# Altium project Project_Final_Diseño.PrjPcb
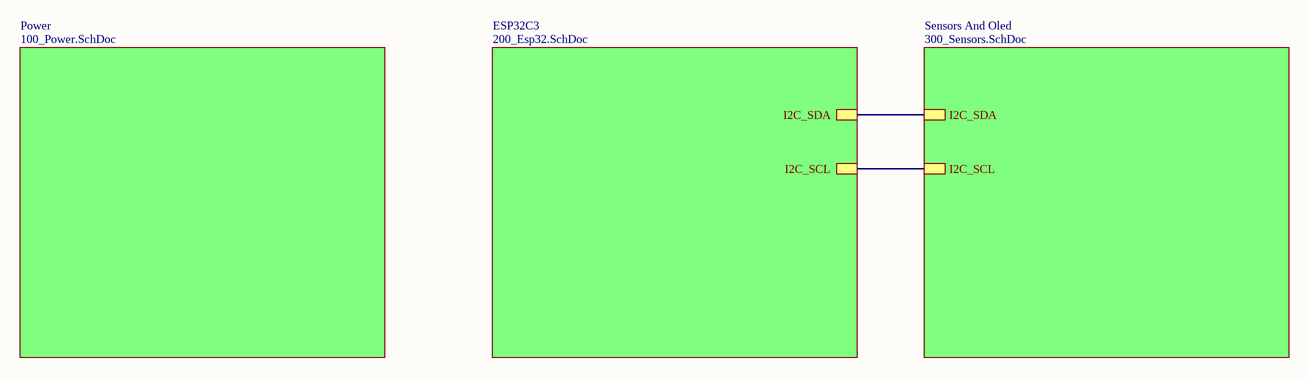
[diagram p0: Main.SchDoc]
4 sheets, 49 parts. Net scope: hierarchical (ports join the sheet entries above them; power ports are global).
Board file: PCB_FINALPcbDoc.PcbDoc
Sheets:
  Main.SchDoc
    Power = 100_Power.SchDoc
    ESP32C3 = 200_Esp32.SchDoc
    Sensors And Oled = 300_Sensors.SchDoc

## Sheet Main.SchDoc
size A4; SheetNumber: 1; SheetTotal: 4

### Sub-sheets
ESP32C3 = 200_Esp32.SchDoc: I2C_SDA, I2C_SCL
Power = 100_Power.SchDoc: no entries
Sensors And Oled = 300_Sensors.SchDoc: I2C_SDA, I2C_SCL

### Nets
NetU203_5: sheet ESP32C3/I2C_SDA, sheet Sensors And Oled/I2C_SDA
NetU203_6: sheet ESP32C3/I2C_SCL, sheet Sensors And Oled/I2C_SCL

## Sheet 100_Power.SchDoc
size A4; SheetNumber: 2; SheetTotal: 4
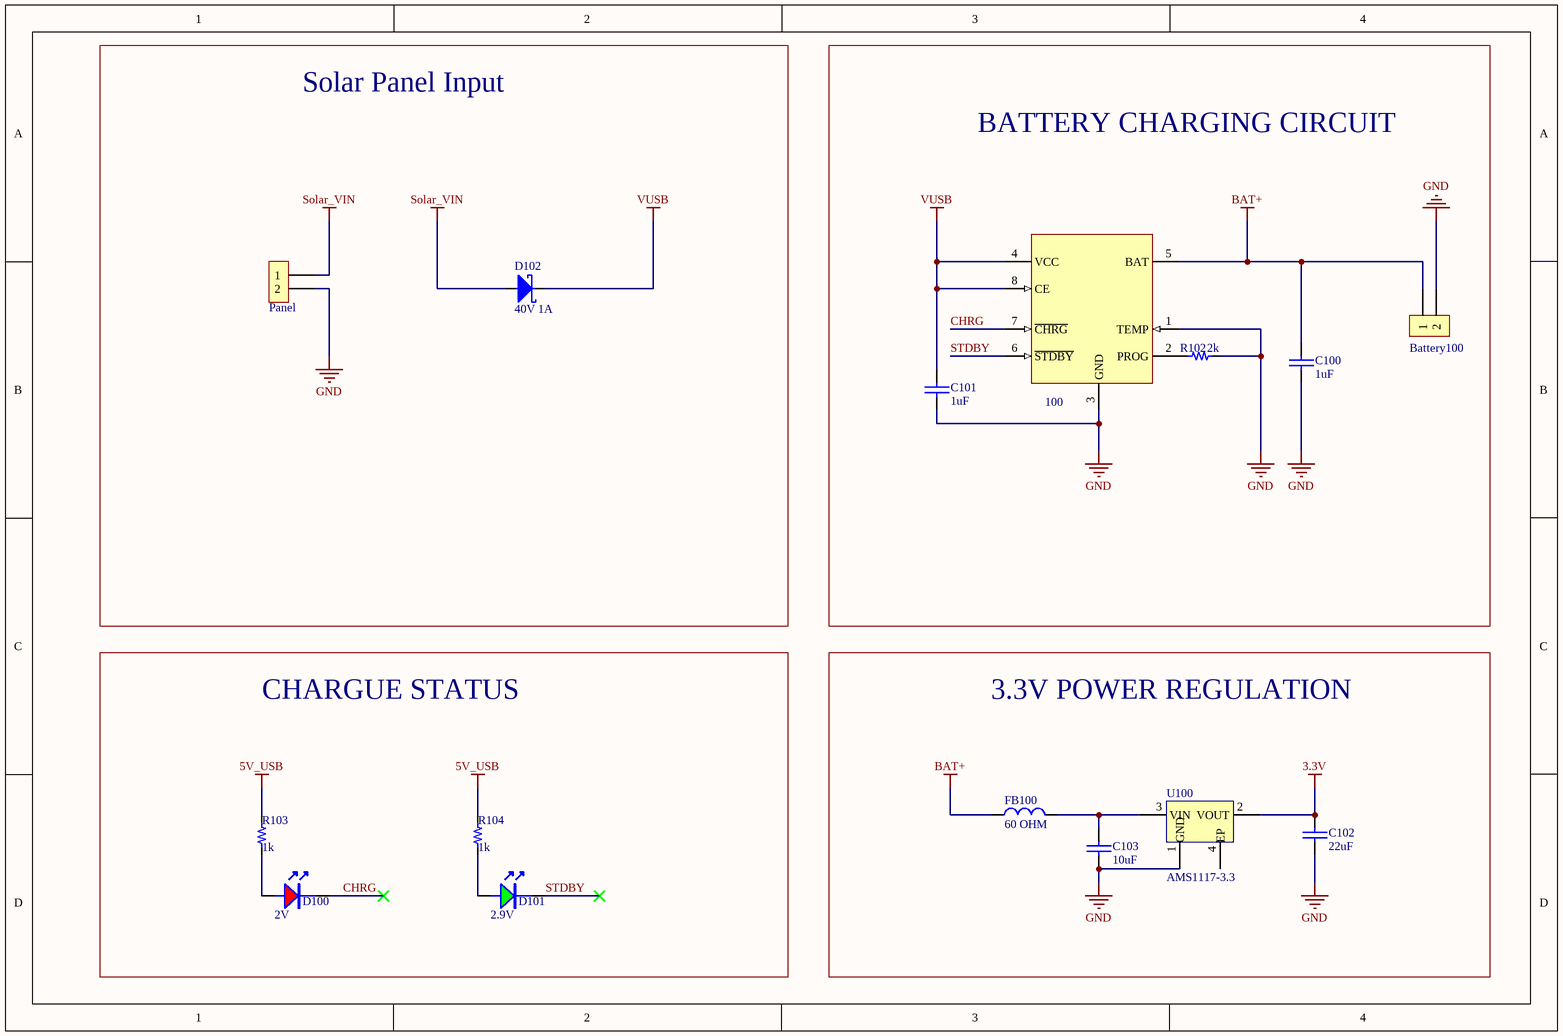
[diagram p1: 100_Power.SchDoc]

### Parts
100  4.2V 1A  [SOIC_8_3.9mm]  (value not drawn)
Battery100  2x1  [H_2x1_TH_100mil]  (value not drawn)  (no BOM)
C100  value 1uF  [0603_cap]  (hidden comment: 1uF 50V)
C101  value 1uF  [0603_cap]  (hidden comment: 1uF 50V)
C102  value 22uF  [0603_cap]  (hidden comment: 22uF 10V)
C103  value 10uF  [0603_cap]  (hidden comment: 10uF 10V)
D100  2V  [0805_LED]
D101  2.9V  [0805_LED]
D102  40V 1A  [SOD_123]
FB100  value 60 OHM  [0603_fb]  (hidden comment: 60OHM 2A)
Panel  2x1  [H_2x1_TH_100mil]  (value not drawn)  (no BOM)
R102  value 2k  [0603_resistor]  (hidden comment: 2K 0603)
R103  value 1k  [0603_res]  (hidden comment: 1k 1/10W)
R104  value 1k  [0603_res]  (hidden comment: 1k 1/10W)
U100  AMS1117-3.3  [SOT_223]

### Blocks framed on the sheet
Solar Panel Input: D102 Panel
BATTERY CHARGING CIRCUIT: 100 Battery100 C100 C101 R102
CHARGUE STATUS: D100 D101 R103 R104
3.3V POWER REGULATION: C102 C103 FB100 U100

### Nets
3.3V: C102.1 U100.2(VOUT)
5V_USB: R103.2 R104.2
BAT+: 100.5(BAT) Battery100.1 C100.1 FB100.1
GND: 100.1(TEMP) 100.3(GND) Battery100.2 C100.2 C101.2 C102.2 C103.2 Panel.2 R102.2 U100.1(GND)
Solar_VIN: D102.2 Panel.1
VUSB: 100.4(VCC) 100.8(CE) C101.1 D102.1
CHRG: 100.7(~{CHRG}) D100.2
STDBY: 100.6(~{STDBY}) D101.2
Net100_2: 100.2(PROG) R102.1
NetC103_1: C103.1 FB100.2 U100.3(VIN)
NetD100_1: D100.1(A) R103.1
NetD101_1: D101.1(A) R104.1

Not connected (* = marked no-connect by the designer): U100 4(EP)

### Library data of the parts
100 = IC_BAT_CHG_4.2V_1A: -300mV~8V Lithium-ion/Polymer 1 1A ESOP-8 Battery Management ROHS; Manufacturer: YONGYUTAI; Manufacturer Part Number: TP4056
Battery100 Panel = H_Male_2x1_TH_100mil
C100 C101 = Cap_1uF_0603_50V: 50V 1uF X5R ±10% 0603 Multilayer Ceramic Capacitors MLCC - SMD/SMT ROHS; Manufacturer: Samsung Electro-Mechanics; Manufacturer Part Number: CL10A105KB8NNNC
C102 = Cap_22uF_0603_10V: 10V 22uF X5R ±20% 0603 Multilayer Ceramic Capacitors MLCC - SMD/SMT ROHS; Manufacturer: HRE; Manufacturer Part Number: CGA0603X5R226M100JT
C103 = Cap_10uF_0603_10V: 10V 10uF X5R ±10% 0603 Multilayer Ceramic Capacitors MLCC - SMD/SMT ROHS; Manufacturer: CCTC; Manufacturer Part Number: TCC0603X5R106K100CT
D100 = LED_0805_RED: LED RED CLEAR 0805 SMD; Manufacturer: XINGLIGHT; Manufacturer Part Number: XL-2012SURC
D101 = LED_0805_Green: LED GREEN CLEAR 0805 SMD; Manufacturer: XINGLIGHT; Manufacturer Part Number: XL-2012UGC
D102 = D_Schottky_40V_1A_SOD_123F: DIODE SCHOTTKY 40V 1A SOD123F; Manufacturer: Shanghai Prisemi Elec; Manufacturer Part Number: PSBD1DF40V1H
FB100 = FB_60_0603_2A: 2A 1 100mΩ 60Ω@100MHz ±25% 0603 Ferrite Beads ROHS; Manufacturer: TAI-TECH; Manufacturer Part Number: HCB1608KF-600T20
R102 = RES_2K_0603_1/10W_1%_1: RES 2K OHM 1% 1/10W 0603; Manufacturer: NIC Components Corp; Manufacturer PN: NRC06F2001TRF
R103 R104 = Res_1k_0603_1/10W: RES SMD 1k OHM 5% 1/10W 0603; Manufacturer: FOJAN; Manufacturer Part Number: FRC0603J102 TS
U100 = LDO_3V3_1A_FIXED: 1A 60dB@(120Hz) Fixed 3.3V Positive 18V SOT-223 Linear Voltage Regulators (LDO) ROHS; Manufacturer: UMW(Youtai Semiconductor Co., Ltd.)

## Sheet 200_Esp32.SchDoc
size A3; SheetNumber: 3; SheetTotal: 4
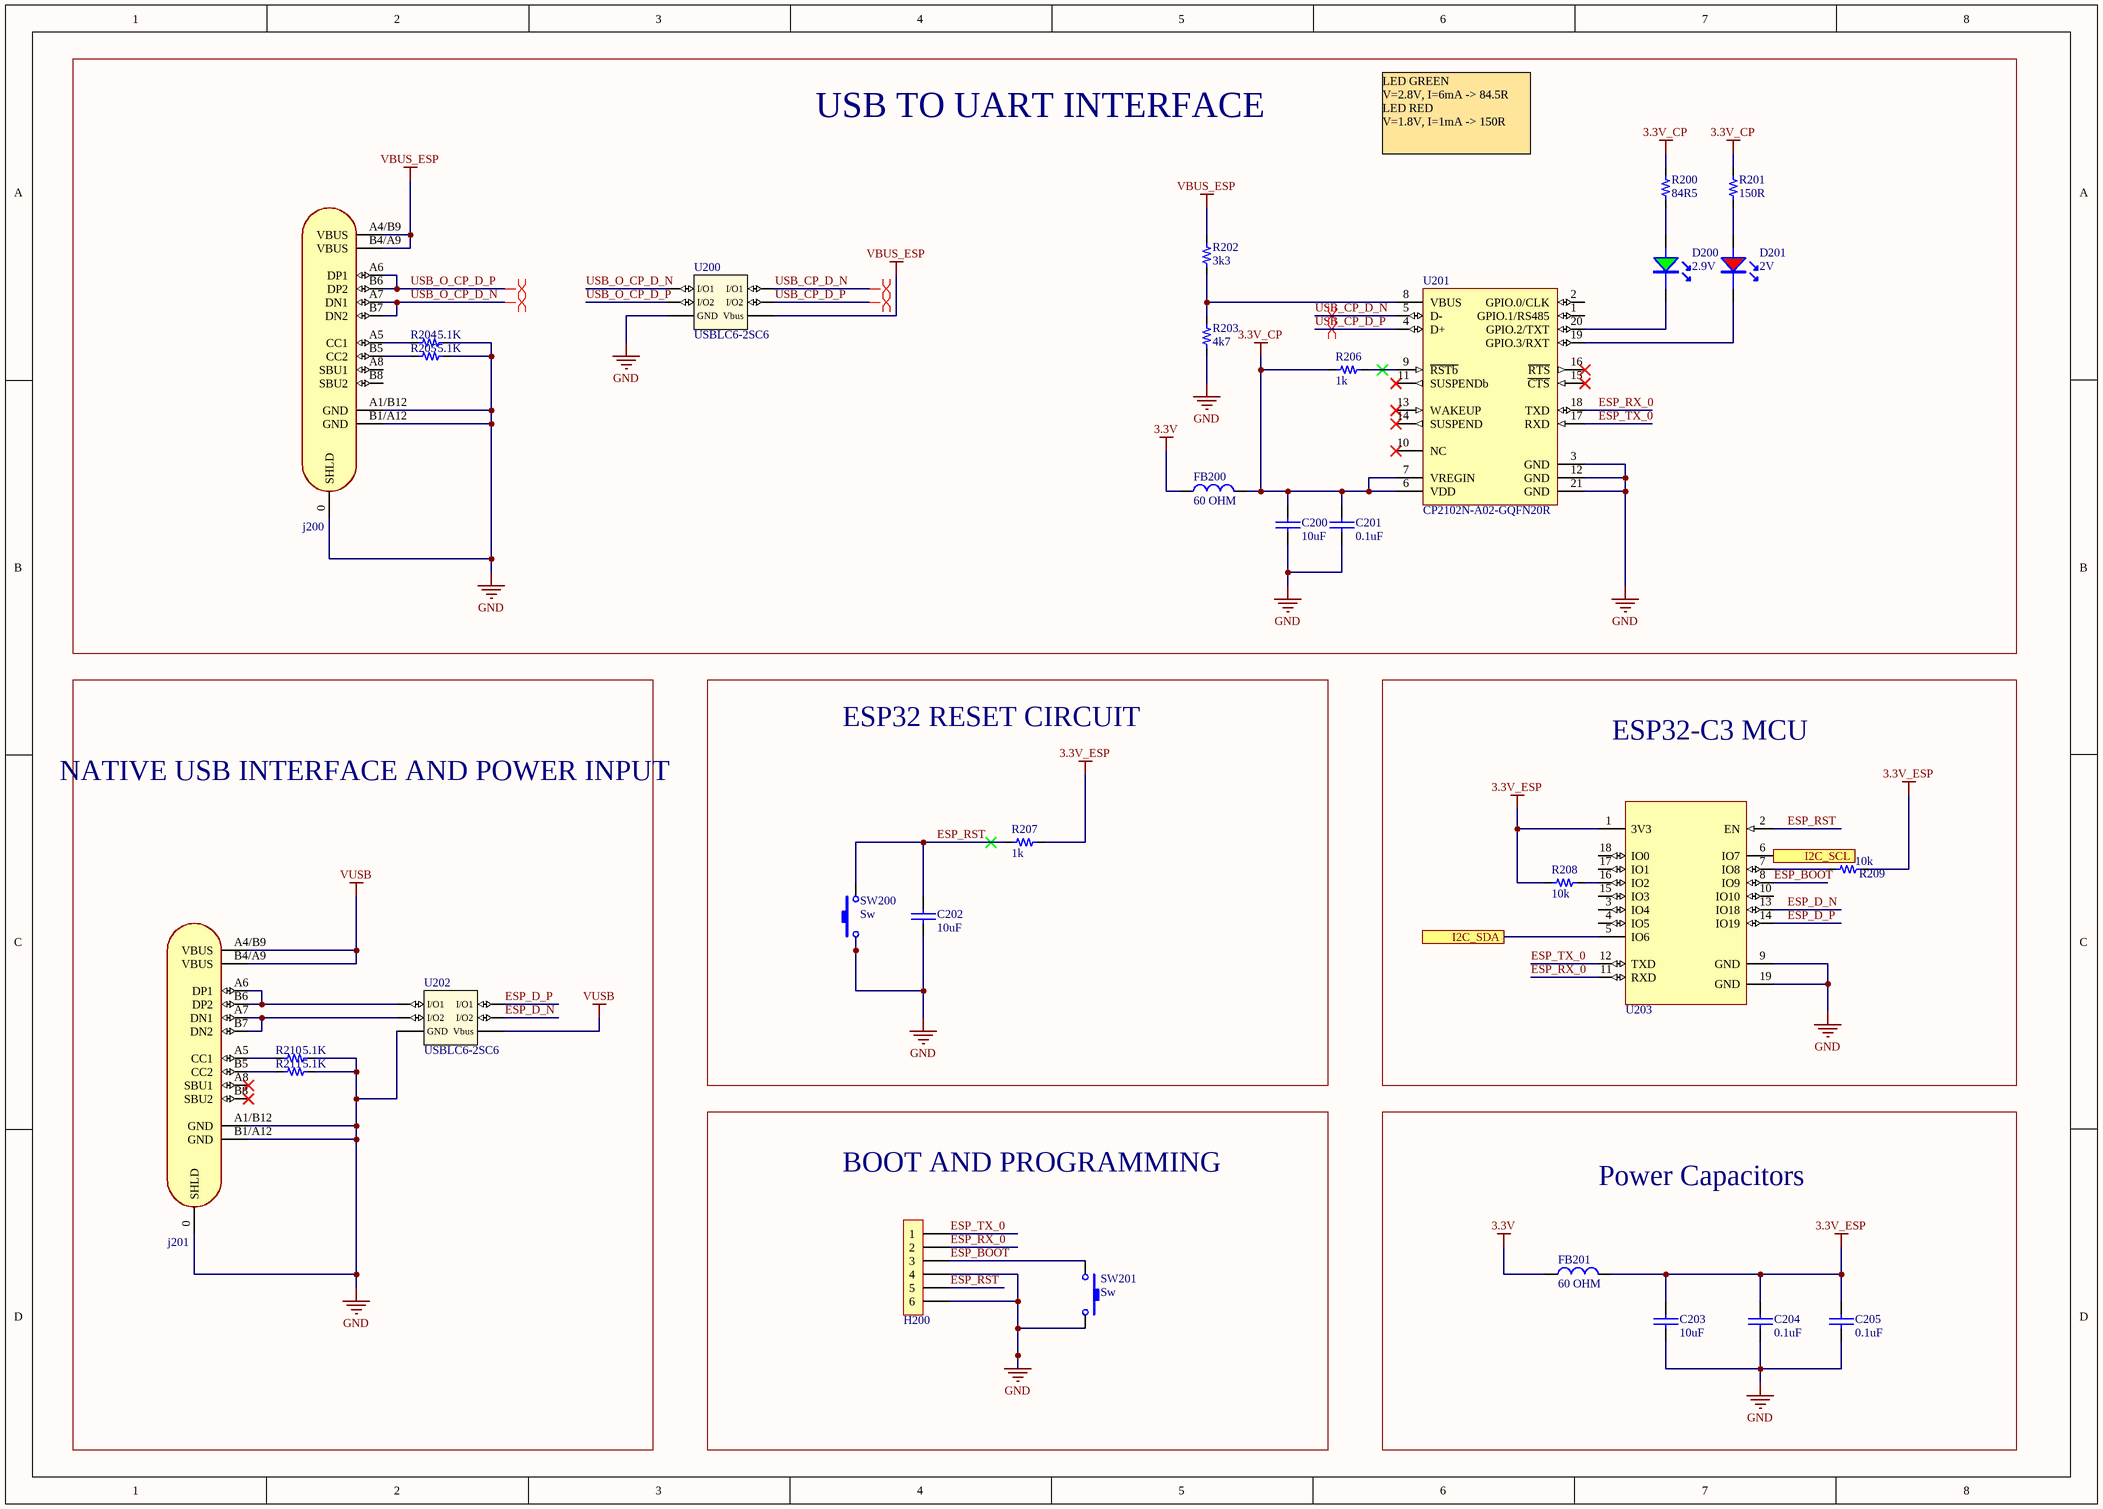
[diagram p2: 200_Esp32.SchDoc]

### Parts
C200  value 10uF  [0603_cap]  (hidden comment: 10uF 10V)
C201  value 0.1uF  [0603_cap]  (hidden comment: 0.1uF 50V)
C202  value 10uF  [0603_cap]  (hidden comment: 10uF 10V)
C203  value 10uF  [0603_cap]  (hidden comment: 10uF 10V)
C204  value 0.1uF  [0603_cap]  (hidden comment: 0.1uF 50V)
C205  value 0.1uF  [0603_cap]  (hidden comment: 0.1uF 50V)
D200  2.9V  [0805_LED]
D201  2V  [0805_LED]
FB200  value 60 OHM  [0603_fb]  (hidden comment: 60OHM 2A)
FB201  value 60 OHM  [0603_fb]  (hidden comment: 60OHM 2A)
H200  6x1  [H_6x1_TH_100mil]  (value not drawn)  (no BOM)
j200  USB C  [CON_USB_C_16P_RA]  (value not drawn)
j201  USB C  [CON_USB_C_16P_RA]  (value not drawn)
R200  value 84R5  [0603_res]  (hidden comment: 84R5 1/10W)
R201  value 150R  [0603_res]  (hidden comment: 150R 1/10W)
R202  value 3k3  [0603_res]  (hidden comment: 3k3 1/10W)
R203  value 4k7  [0603_res]  (hidden comment: 4k7 1/10W)
R204  value 5.1K  [0603_res]  (hidden comment: 5.1K 1/10W)
R205  value 5.1K  [0603_res]  (hidden comment: 5.1K 1/10W)
R206  value 1k  [0603_res]  (hidden comment: 1k 1/10W)
R207  value 1k  [0603_res]  (hidden comment: 1k 1/10W)
R208  value 10k  [0603_res]  (hidden comment: 10k 1/10W)
R209  value 10k  [0603_res]  (hidden comment: 10k 1/10W)
R210  value 5.1K  [0603_res]  (hidden comment: 5.1K 1/10W)
R211  value 5.1K  [0603_res]  (hidden comment: 5.1K 1/10W)
SW200  Sw  [Sw_PUSH_4.5x4.5x5mm]
SW201  Sw  [Sw_PUSH_4.5x4.5x5mm]
U200  USBLC6-2SC6  [SOT_23_6]
U201  CP2102N-A02-GQFN20R  [WFQFN_20_EP_3X3MM]
U202  USBLC6-2SC6  [SOT_23_6]
U203  ESP32-C3-WROOM-02-N4  [ESP32-C3-WROOM-02-N4]  (value not drawn)

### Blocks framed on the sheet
USB TO UART INTERFACE: C200 C201 D200 D201 FB200 j200 R200-R206 U200 U201
ESP32 RESET CIRCUIT: C202 R207 SW200
ESP32-C3 MCU: R208 R209 U203
BOOT AND PROGRAMMING: H200 SW201
Power Capacitors: C203-C205 FB201

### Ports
I2C_SCL, I2C_SDA

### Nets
3.3V: FB200.1 FB201.1
3.3V_CP: C200.1 C201.1 FB200.2 R200.2 R201.2 R206.1 U201.6(VDD) U201.7(VREGIN)
3.3V_ESP: C203.1 C204.1 C205.1 FB201.2 R207.2 R208.1 R209.2 U203.1(3V3)
GND: C200.2 C201.2 C202.2 C203.2 C204.2 C205.2 H200.4 H200.6 j200.0(SHLD) j200.A1/B12(GND) j200.B1/A12(GND) j201.0(SHLD) j201.A1/B12(GND) j201.B1/A12(GND) R203.1 R204.2 R205.2 R210.2 R211.2 SW200.1 SW201.2 U200.2(GND) U201.3(GND) U201.12(GND) U201.21(GND) U202.2(GND) U203.9(GND) U203.19(GND)
VBUS_ESP: j200.A4/B9(VBUS) j200.B4/A9(VBUS) R202.2 U200.5(Vbus)
VUSB: j201.A4/B9(VBUS) j201.B4/A9(VBUS) U202.5(Vbus)
ESP_BOOT: H200.3 SW201.1 U203.8(IO9)
ESP_D_N: U202.4(I/O2) U203.13(IO18)
ESP_D_P: U202.6(I/O1) U203.14(IO19)
ESP_RST: C202.1 H200.5 R207.1 SW200.2 U203.2(EN)
ESP_RX_0: H200.2 U201.18(TXD) U203.11(RXD)
ESP_TX_0: H200.1 U201.17(RXD) U203.12(TXD)
USB_CP_D_N: U200.6(I/O1) U201.5(D-)
USB_CP_D_P: U200.4(I/O2) U201.4(D+)
USB_O_CP_D_N: j200.A7(DN1) j200.B7(DN2) U200.1(I/O1)
USB_O_CP_D_P: j200.A6(DP1) j200.B6(DP2) U200.3(I/O2)
NetD200_1: D200.1(A) R200.1
NetD200_2: D200.2 U201.20(GPIO.2/TXT)
NetD201_1: D201.1(A) R201.1
NetD201_2: D201.2 U201.19(GPIO.3/RXT)
Netj200_A5: j200.A5(CC1) R204.1
Netj200_B5: j200.B5(CC2) R205.1
Netj201_A5: j201.A5(CC1) R210.1
Netj201_A6: j201.A6(DP1) j201.B6(DP2) U202.1(I/O1)
Netj201_A7: j201.A7(DN1) j201.B7(DN2) U202.3(I/O2)
Netj201_B5: j201.B5(CC2) R211.1
NetR202_1: R202.1 R203.2 U201.8(VBUS)
NetR206_2: R206.2 U201.9(~{RSTb})
NetR208_2: R208.2 U203.16(IO2)
NetR209_1: R209.1 U203.7(IO8)
NetU203_5: U203.5(IO6) ; port I2C_SDA
NetU203_6: U203.6(IO7) ; port I2C_SCL

Not connected (* = marked no-connect by the designer): j200 A8(SBU1) B8(SBU2); j201 A8(SBU1)* B8(SBU2)*; U201 1(GPIO.1/RS485) 2(GPIO.0/CLK) 10(NC)* 11(SUSPENDb)* 13(WAKEUP)* 14(SUSPEND)* 15(~{CTS})* 16(~{RTS})*; U203 3(IO4) 4(IO5) 10(IO10) 15(IO3) 17(IO1) 18(IO0)

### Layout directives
differential pair: USB_CP_D_N, USB_CP_D_P, USB_O_CP_D_N, USB_O_CP_D_P

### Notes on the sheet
- LED GREEN
  V=2.8V, I=6mA -> 84.5R
  LED RED
  V=1.8V, I=1mA -> 150R
- NATIVE USB INTERFACE AND POWER INPUT

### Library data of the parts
C200 C202 C203 = Cap_10uF_0603_10V: as C103 on sheet 100_Power
C201 C204 C205 = Cap_0.1uF_0603_50V: 50V 100nF Y5V -20%~+80% 0603 Multilayer Ceramic Capacitors MLCC - SMD/SMT ROHS; Manufacturer: Walsin Tech Corp; Manufacturer Part Number: 0603F104Z500CT
D200 = LED_0805_Green: as D101 on sheet 100_Power
D201 = LED_0805_RED: as D100 on sheet 100_Power
FB200 FB201 = FB_60_0603_2A: as FB100 on sheet 100_Power
H200 = H_Male_6x1_TH_100mil
j200 j201 = CON_USB_TYPEC_16P: 3A USB 3.1 1 Surface Mount 16P Female -40℃~+85℃ Type-C SMD USB Connectors ROHS; Manufacturer: SHOU HAN; Manufacturer Part Number: TYPE-C-3.1-16PIN
R200 = Res_84R5_0603_1/10W: 100mW Thick Film Resistor 50V ±100ppm/℃ ±1% 84.5Ω 0603 Chip Resistor - Surface Mount ROHS; Manufacturer: LIZ Elec; Manufacturer Part Number: CR0603FA84R5G
R201 = Res_150R_0603_1/10W: 100mW Thick Film Resistor 75V ±100ppm/℃ ±1% 150Ω 0603 Chip Resistor - Surface Mount ROHS; Manufacturer: RALEC; Manufacturer Part Number: RTT031500FTP
R202 = Res_3k3_0603_1/10W: RES SMD 3k3 OHM 5% 1/10W 0603; Manufacturer: FOJAN; Manufacturer Part Number: FRC0603J332 TS
R203 = Res_4k7_0603_1/10W: 100mW Thick Film Resistor 75V ±1% 4.7kΩ 0603 Chip Resistor - Surface Mount ROHS; Manufacturer: VO; Manufacturer Part Number: SCR0603F4K7
R204 R205 R210 R211 = Res_5.1K_0603_1/10W: 5.1 kOhms ±1% 0.1W, 1/10W Chip Resistor 0603 (1608 Metric) Automotive AEC-Q200 Thick Film; Manufacturer: KOA Speer Electronics, Inc.; Manufacturer Part Number: RK73H1JTTD5101F
R206 R207 = Res_1k_0603_1/10W: as R103 on sheet 100_Power
R208 R209 = Res_10k_0603_1/10W: RES SMD 10k OHM 5% 1/10W 0603; Manufacturer: FOJAN; Manufacturer Part Number: FRC0603J103TS
SW200 SW201 = Sw_PUSH_4.5x4.5x5.0xmm: SWITCH TACTILE SPST-NO 0.05A 12V; Manufacturer: BZCN; Manufacturer Part Number: TSC015A05026A
U200 U202 = TVS_5.25V_2CH_SOT_23_6: TVS DIODE 5.25V 17V SOT23-6; Manufacturer: STMicroelectronics
U201 = IC_SGL_USB2UART-BRIDGE_20QFN: IC USB TO UART BRIDGE QFN20; Manufacturer: Silicon Labs
U203 = MCU_ESP32-C3-WROOM-02-N4: RF TXRX MOD BT WIFI PCB TH SMD; Manufacturer: Espressif Systems

## Sheet 300_Sensors.SchDoc
size A4; SheetNumber: 4; SheetTotal: 4
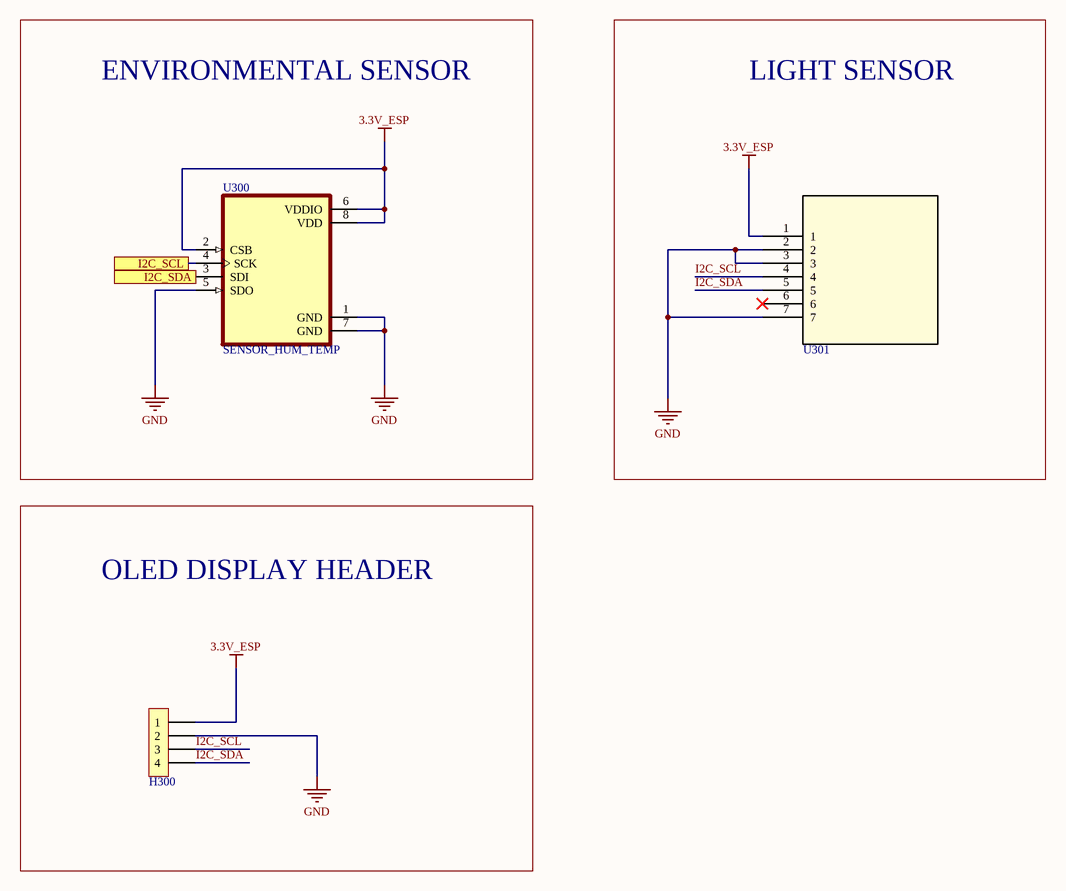
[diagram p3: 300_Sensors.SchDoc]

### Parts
H300  4x1  [H_4x1_TH_2.54mm]  (value not drawn)  (no BOM)
U300  SENSOR_HUM_TEMP  [BME280_SENSOR_TEMP_HUM]
U301  BH17-Sensor  [BH1750FVI-TR_ROM]  (value not drawn)

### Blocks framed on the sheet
ENVIRONMENTAL SENSOR: U300
LIGHT SENSOR: U301
OLED DISPLAY HEADER: H300

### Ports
I2C_SCL, I2C_SDA

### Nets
3.3V_ESP: H300.1 U300.2(CSB) U300.6(VDDIO) U300.8(VDD) U301.1
GND: H300.2 U300.1(GND) U300.5(SDO) U300.7(GND) U301.2 U301.3 U301.7
I2C_SCL: H300.3 U301.4
I2C_SDA: H300.4 U301.5
NetU203_5: U300.3(SDI) ; port I2C_SDA
NetU203_6: U300.4(SCK) ; port I2C_SCL

Not connected (* = marked no-connect by the designer): U301 6*

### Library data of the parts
H300 = H_Male_4x1_TH_100mil
U300 = BME280_SENSOR_HUM_TEMP: SENSOR PRESSURE HUMIDITY TEMP; Manufacturer: Bosch Sensortec; Manufacturer PN: BME280
U301 = BH1750FVI-TR: SENSOR OPT 560NM AMBIENT 6WSOF; Manufacturer: Rohm Semiconductor

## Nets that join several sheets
3.3V: 100_Power (C102.1 U100.2), 200_Esp32 (FB200.1 FB201.1)
3.3V_ESP: 200_Esp32 (8 pins), 300_Sensors (5 pins)
GND: 100_Power (10 pins), 200_Esp32 (28 pins), 300_Sensors (7 pins)
VUSB: 100_Power (100.4 100.8 C101.1 D102.1), 200_Esp32 (j201.A4/B9 j201.B4/A9 U202.5)
NetU203_5: 200_Esp32 (U203.5), 300_Sensors (U300.3)
NetU203_6: 200_Esp32 (U203.6), 300_Sensors (U300.4)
